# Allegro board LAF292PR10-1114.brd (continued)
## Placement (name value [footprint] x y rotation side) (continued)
CZ84  68P_0402_50V8J  [C_0402]  181.78 36.2 0 bottom
CZ85  68P_0402_50V8J  [C_0402]  178.48 37.3 90 bottom
CZ86  68P_0402_50V8J  [C_0402]  177.59 37.3 90 bottom
CZ87  68P_0402_50V8J  [C_0402]  176.7 37.3 90 bottom
CZ88  68P_0402_50V8J  [C_0402]  174.29 36.6 90 bottom
CZ89  68P_0402_50V8J  [C_0402]  173.4 36.6 90 bottom
CZ90  0.1U_0201_10V6K  [C_0201]  175.94 36.92 90 bottom
CZ91  0.1U_0201_10V6K  [C_0201]  179.24 37.17 90 bottom
CZ92  0.1U_0201_10V6K  [C_0201]  179.87 37.17 90 bottom
CZ100  1U_0402_6.3V6K  [C_0402]  162.22 92.54 0 top
CZ101  0.1U_0201_10V6K  [C_0201]  157.4 92.41 270 top
CZ102  1U_0402_6.3V6K  [C_0402]  95.18 46.88 90 top
CZ103  0.1U_0201_10V6K  [C_0201]  94.4 43.81 270 top
CZ104  0.1U_0402_10V7K  [C_0402]  92.28 39.93 0 top
CZ105  1U_0402_6.3V6K  [C_0402]  170.02 82.81 90 bottom
CZ106  0.1U_0201_10V6K  [C_0201]  175.11 79.16 0 bottom
CZ109  470P_0402_50V7K  [C_0402]  233.72 37.7 90 top
CZ112  0.1U_0201_10V6K  [C_0201]  236.26 36.19 270 top
CZ113  470P_0402_50V7K  [C_0402]  234.64 37.7 90 top
CZ114  1000P_0402_50V7K  [C_0402]  19.35 32.09 180 top
CZ115  0.1U_0201_10V6K  [C_0201]  19.5 32.82 180 top
CZ116  0.1U_0201_10V6K  [C_0201]  201.9 42.31 90 top
CZ117  470P_0402_50V7K  [C_0402]  202.66 42.4 90 top
CZ118  470P_0402_50V7K  [C_0402]  203.61 42.4 90 top
CZ119  0.1U_0201_10V6K  [C_0201]  204.37 42.31 90 top
CZ120  0.1U_0201_10V6K  [C_0201]  224.91 43.49 0 top
CZ121  470P_0402_50V7K  [C_0402]  225.01 42.68 270 top
CZ122  0.1U_0201_10V6K  [C_0201]  232.71 37.89 90 top
CZ124  2200P_0402_50V7K  [C_0402]  205.13 42.4 90 top
CZ125  0.1U_0201_10V6K  [C_0201]  256.79 34.66 0 top
CZ126  220P_0402_50V7K  [C_0402]  256.87 33.9 0 top
CZ127  1000P_0402_50V7K  [C_0402]  256.87 32.95 0 top
CZ128  0.1U_0201_10V6K  [C_0201]  256.79 32.19 0 top
CZ150  0.1U_0402_10V7K  [C_0402]  228.95 57.38 90 top
CZ151  0.1U_0402_10V7K  [C_0402]  227.99 57.38 90 top
CZ152  0.22U_0402_10V6K  [C_0402]  226.79 57.38 90 top
CZ153  0.22U_0402_10V6K  [C_0402]  225.84 57.38 90 top
CZ154  .1U_0402_16V7K  [C_0402]  232.05 62.54 0 top
CZ155  .1U_0402_16V7K  [C_0402]  223.69 61.86 90 top
CZ164  100P_0402_50V8J  [C_0402]  235.5 49.49 90 bottom
CZ165  100P_0402_50V8J  [C_0402]  232.17 51.05 0 top
CZ166  100P_0402_50V8J  [C_0402]  232.17 52 0 top
CZ167  0.1U_0201_10V6K  [C_0201]  103.04 91.74 90 top
CZ168  10U_0603_10V6M  [C_0603]  276.14 86.19 180 top
CZ169  0.1U_0201_10V6K  [C_0201]  276.13 87.14 0 top
CZ170  0.1U_0201_10V6K  [C_0201]  276.06 88.67 0 top
CZ180  68P_0402_50V8J  [C_0402]  32.28 85.45 0 bottom
CZ181  68P_0402_50V8J  [C_0402]  32.41 87.99 0 bottom
CZ182  68P_0402_50V8J  [C_0402]  32.35 83.91 0 bottom
CZ183  68P_0402_50V8J  [C_0402]  32.35 83.02 0 bottom
CZ184  68P_0402_50V8J  [C_0402]  32.35 82.13 0 bottom
CZ185  68P_0402_50V8J  [C_0402]  32.35 81.24 0 bottom
CZ186  0.1U_0201_10V6K  [C_0201]  32.45 84.69 0 bottom
CZ187  0.1U_0201_10V6K  [C_0201]  32.45 87.23 0 bottom
CZ188  0.1U_0201_10V6K  [C_0201]  82.58 90.63 90 bottom
CZ197  470P_0402_50V7K  [C_0402]  219.18 42.79 180 top
CZ198  100P_0402_50V8J  [C_0402]  225.47 89.49 270 top
CZ200  0.1U_0402_25V6K  [C_0402]  231.16 34.97 0 bottom
CZ300  68P_0402_50V8J  [C_0402]  226.62 72.11 180 top
CZ301  68P_0402_50V8J  [C_0402]  226.37 73.11 180 top
CZ302  68P_0402_50V8J  [C_0402]  226.37 74.06 180 top
CZ303  68P_0402_50V8J  [C_0402]  227.07 74.98 180 top
CZ304  68P_0402_50V8J  [C_0402]  229.4 78.57 180 top
CZ305  0.1U_0201_10V6K  [C_0201]  186.61 37.64 90 top
CZ306  470P_0402_50V7K  [C_0402]  185.03 36.15 180 top
DA1  AZ5125-02S.R7G_SOT23-3  [AZ5125-02SPR7G_SOT23-3]  281.14 33.52 270 top
DA2  AZ5125-02S.R7G_SOT23-3  [AZ5125-02SPR7G_SOT23-3]  283.2 29.58 90 top
DA3  AZ5123-02S.R7G_SOT23-3  [L03ESDL5V0CC3-2_SOT23-3]  280.94 39.33 270 top
DA6  AZ5125-02S.R7G_SOT23-3  [AZ5125-02SPR7G_SOT23-3]  286.45 23.45 90 top
DA7  AZ5125-02S.R7G_SOT23-3  [AZ5125-02SPR7G_SOT23-3]  295.72 23.43 90 top
DA8  RB751S-40 SOD-523  [AZ5125-01HPR7G_SOD523-2]  257.36 38.46 0 top
DC1  RB751S-40 SOD-523  [AZ5125-01HPR7G_SOD523-2]  167.68 34.3 270 top
DC2  RB751S-40 SOD-523  [AZ5125-01HPR7G_SOD523-2]  169.69 42.8 270 top
DE1  BZV55-B5V6_SOD80C2  [BZV55-B5V1_SOD80C2]  176.7 70.57 270 top
DE2  RB751S-40 SOD-523  [AZ5125-01HPR7G_SOD523-2]  262.93 82.09 270 top
DI1  AZ1045-04F_DFN2510P10E-10-9  [L05ESDL5V0NA-4_SLP2510P8-10-9]  15.48 22.2 270 bottom
DI2  -  [PESD5V0U2BT_SOT23-3]  24.88 24.75 90 top
DI4  AZ1045-04F_DFN2510P10E-10-9  [L05ESDL5V0NA-4_SLP2510P8-10-9]  280.96 70.72 90 top
DI5  -  [PESD5V0U2BT_SOT23-3]  278.96 73.36 90 top
DT1  DA2J10100L SOD323  [1N4148WS-7-F_SOD323-2]  31.01 31.68 180 top
DT2  DA2J10100L SOD323  [1N4148WS-7-F_SOD323-2]  31.01 33.46 180 top
DT3  DA2J10100L SOD323  [1N4148WS-7-F_SOD323-2]  25.05 33.45 270 top
DT4  AZ4024-02S_SOT23-3  [L30ESD24VC3-2_SOT23-3]  17.98 80.22 270 bottom
DT5  AZ5B75-01B.R7G CSP0603P2Y  [ESD8011MUT5G_X3DFN2-2-S]  13 86.48 90 top
DT6  AZ5B75-01B.R7G CSP0603P2Y  [ESD8011MUT5G_X3DFN2-2-S]  13 85.77 270 top
DT9  AZ5B75-01B.R7G CSP0603P2Y  [ESD8011MUT5G_X3DFN2-2-S]  13 79.37 90 top
DT10  AZ5B75-01B.R7G CSP0603P2Y  [ESD8011MUT5G_X3DFN2-2-S]  13 78.66 270 top
DT13  AZ5B75-01B.R7G CSP0603P2Y  [ESD8011MUT5G_X3DFN2-2-S]  13 86.48 90 bottom
DT14  AZ5B75-01B.R7G CSP0603P2Y  [ESD8011MUT5G_X3DFN2-2-S]  13 85.77 270 bottom
DT17  AZ5B75-01B.R7G CSP0603P2Y  [ESD8011MUT5G_X3DFN2-2-S]  13 78.66 270 bottom
DT18  AZ5B75-01B.R7G CSP0603P2Y  [ESD8011MUT5G_X3DFN2-2-S]  13 79.37 90 bottom
DT21  AZ4024-02S_SOT23-3  [L30ESD24VC3-2_SOT23-3]  16.01 61.05 270 bottom
DT22  AZ5B75-01B.R7G CSP0603P2Y  [ESD8011MUT5G_X3DFN2-2-S]  13 72.13 90 top
DT23  AZ5B75-01B.R7G CSP0603P2Y  [ESD8011MUT5G_X3DFN2-2-S]  13 71.42 270 top
DT26  AZ5B75-01B.R7G CSP0603P2Y  [ESD8011MUT5G_X3DFN2-2-S]  13 64.64 90 top
DT27  AZ5B75-01B.R7G CSP0603P2Y  [ESD8011MUT5G_X3DFN2-2-S]  13 63.93 270 top
DT30  AZ5B75-01B.R7G CSP0603P2Y  [ESD8011MUT5G_X3DFN2-2-S]  13 72.13 90 bottom
DT31  AZ5B75-01B.R7G CSP0603P2Y  [ESD8011MUT5G_X3DFN2-2-S]  13 71.42 270 bottom
DT34  AZ5B75-01B.R7G CSP0603P2Y  [ESD8011MUT5G_X3DFN2-2-S]  13 63.93 270 bottom
DT35  AZ5B75-01B.R7G CSP0603P2Y  [ESD8011MUT5G_X3DFN2-2-S]  13 64.64 90 bottom
DT38  DA2J10100L SOD323  [1N4148WS-7-F_SOD323-2]  26.83 33.45 270 top
DT41  AZ1045-04F_DFN2510P10E-10-9  [L05ESDL5V0NA-4_SLP2510P8-10-9]  13.56 82.02 270 top
DT42  AZ1045-04F_DFN2510P10E-10-9  [L05ESDL5V0NA-4_SLP2510P8-10-9]  14.07 84.14 90 bottom
DT43  AZ1045-04F_DFN2510P10E-10-9  [L05ESDL5V0NA-4_SLP2510P8-10-9]  13.56 67.03 270 top
DT44  AZ1045-04F_DFN2510P10E-10-9  [L05ESDL5V0NA-4_SLP2510P8-10-9]  14.07 69.16 90 bottom
DV1  BAT54CW SOT323  [BAT54CW_SOT323-3]  219.68 31.93 180 bottom
DV2  BAT54CW SOT323  [BAT54CW_SOT323-3]  216.88 31.93 180 bottom
DV3  BAT54CW SOT323  [BAT54CW_SOT323-3]  235.12 27.52 180 top
DV4  -  [PESD5V0U2BT_SOT23-3]  181.12 37.71 90 top
DZ1  RB751S-40 SOD-523  [AZ5125-01HPR7G_SOD523-2]  236.99 42.25 0 top
DZ2  RB751S-40 SOD-523  [AZ5125-01HPR7G_SOD523-2]  238.17 43.65 0 top
DZ5  RB751S-40 SOD-523  [AZ5125-01HPR7G_SOD523-2]  228.9 85.48 0 top
DZ6  RB751S-40 SOD-523  [AZ5125-01HPR7G_SOD523-2]  229.06 79.84 90 top
DZ7  RB751S-40 SOD-523  [AZ5125-01HPR7G_SOD523-2]  189.51 36.95 270 top
DZ8  RB751S-40 SOD-523  [AZ5125-01HPR7G_SOD523-2]  191.09 34.25 180 top
DZ9  -  [BAT54CW_SOT323-3]  236.58 29.3 270 bottom
DZ100  RB751S-40 SOD-523  [AZ5125-01HPR7G_SOD523-2]  233.3 66.11 180 top
DZ101  RB751S-40 SOD-523  [AZ5125-01HPR7G_SOD523-2]  233.3 64.09 180 top
DZ102  RB751S-40 SOD-523  [AZ5125-01HPR7G_SOD523-2]  233.85 56.49 180 top
DZ103  RB751S-40 SOD-523  [AZ5125-01HPR7G_SOD523-2]  233.66 54.85 180 top
DZ104  RB751S-40 SOD-523  [AZ5125-01HPR7G_SOD523-2]  246.28 80.1 0 top
DZ105  RB751S-40 SOD-523  [AZ5125-01HPR7G_SOD523-2]  246.32 81.82 0 top
DZ106  RB751S-40 SOD-523  [AZ5125-01HPR7G_SOD523-2]  255.25 50 180 top
DZ107  RB751S-40 SOD-523  [AZ5125-01HPR7G_SOD523-2]  263.82 46.82 180 top
FD1  FIDUCIAL MARK~D  [FIDUCIAL_C40M80]  18.58 17.26 0 top
FD2  FIDUCIAL MARK~D  [FIDUCIAL_C40M80]  18.58 17.26 180 bottom
FD3  FIDUCIAL MARK~D  [FIDUCIAL_C40M80]  266.74 87.84 0 top
FD4  FIDUCIAL MARK~D  [FIDUCIAL_C40M80]  255.8 88.83 180 bottom
H1  -  [H_3P8]  107.6 80 0 top
H2  -  [H_3P8]  107.6 57.86 0 top
H3  -  [H_3P8]  167.4 80 0 top
H4  -  [H_3P8]  167.4 57.9 0 top
H5  -  [H_1P1N]  117.15 83.46 0 top
H6  -  [H_1P1N]  158.26 60.35 0 top
H7  -  [H_7P0N]  277.95 79.4 0 top
H8  -  [H_7P0N]  276.55 46.9 0 top
H9  -  [H_2P3]  5.5 91.05 0 top
H11  -  [H_2P5]  54.1 91.55 0 top
H12  -  [H_2P3]  90.5 93.2 0 top
H13  -  [H_2P5]  134.43 92.45 0 top
H14  -  [H_2P3]  150.5 93.2 0 top
H16  -  [H_2P3]  234.9 94.9 0 top
H17  -  [H_2P5N]  291 82 0 top
H18  -  [H_2P3]  296 80.5 0 top
H19  -  [H_2P3]  5.5 59.85 0 top
H20  -  [H_2P3]  69.9 65.8 0 top
H24  -  [H_5P6]  7 4 0 top
H26  -  [H_2P3]  285 4 0 top
H27  -  [H_5P6]  294 4 0 top
H28  -  [H_1P3N]  9.5 75.45 0 top
H29  -  [H_1P3X1P8N]  9.5 59.85 180 top
H30  -  [H_0P8N]  296.5 54.7 0 top
H31  -  [H_0P8N]  295.35 55.5 0 top
H32  -  [H_0P9N]  282.3 46.3 0 top
H33  -  [H_1P1N]  284.5 43 0 top
H34  -  [H_3P2]  177.5 87 0 top
JAPS1  CVILU_CF4218FH0R0-05-NH  [CVILU_CF4218FH0R0-05-NH_18P-T]  194.84 42.28 180 top
JDEG1  JXT_FP241AH-010GAAM  [JXT_FP241AH-010GAAM_10P]  245.03 29.8 180 bottom
JEDP1  ACES_50398-04041-001  [ACES_50398-04041-001_40P]  228.25 38.55 180 bottom
JESPI  JXT_FP241AH-010GAAM  [JXT_FP241AH-010GAAM_10P]  192.48 30.94 0 top
JFAN1  ACES_50278-0040N-001  [ACES_50278-0040N-001_4P]  166.83 71.88 270 bottom
JHDMI1  CONCR_099A3AC19JBLCNF  [CONCR_099A3AC19JBLCNF_19P]  11.6 42.6 90 bottom
JHP1  SINGA_2SJ3095-085111F  [SINGA_2SJ3095-085111F_6P]  287.9 37.1 90 bottom
JIR1  ACES_50208-0060N-P01  [ACES_50208-0060N-P01_6P]  172 50.7 270 bottom
JKBTP1  CVILU_CF5020FD0RK-05-NH  [CVILU_CF5020FD0RK-05-NH_20P-T]  182.25 34.92 180 bottom
JLED1  CVILU_CF61062D0R0-05-NH  [CVILU_CF61062D0R0-05-NH_6P]  30.3 25.95 270 bottom
JNGFF1  LOTES_APCI0241-P001A  [LOTES_APCI0241-P001A_75P-T]  240.74 56.15 270 bottom
JNGFF2  LOTES_APCI0242-P001A  [LOTES_APCI0242-P001A_75P-T]  230.14 88.65 270 bottom
JNGFF3  LOTES_YPCI0016-P003A  [LOTES_YPCI0016-P003A_75P]  34.35 14.25 180 bottom
JPWR1  ACES_50208-0060N-P01  [ACES_50208-0060N-P01_6P]  297.5 25 180 bottom
JRTC1  ACES_50271-0020N-001  [ACES_50271-0020N-001_2P]  288.87 21.4 0 top
JSAR1  ACES_50208-0040N-001  [ACES_50208-0040N-001_4P]  234 49 90 bottom
JSD1  T-SOL_158-1240902600  [T-SOL_158-1240902600_23P-T]  286.35 51.47 90 top
JSEN2  ACES_50208-01201-P01  [ACES_50208-01201-P01_12P]  234 55.8 90 bottom
JSIM1  JAE_SF51S006V4B  [JAE_SF51S006V4B_10P-T]  285.13 53.31 270 bottom
JSPI1  ACES_50696-0200M-P01  [ACES_50696-0200M-P01_20P]  174.29 53.57 90 top
JSPK1  ACES_50278-00601-001  [ACES_50278-00601-001_6P-T]  281.95 18.13 270 bottom
JTAG1  @SHORT PADS~D  [SHORTPADS]  278.94 66.89 90 top
JTS1  ACES_50208-01001-P03  [ACES_50208-01001-P03_10P]  186.7 40.5 0 bottom
JTUN1  ACES_50208-00801-003  [ACES_50208-00801-003_8P]  29.3 82.5 0 bottom
JUSB1  SANTA_375230-1  [SANTA_375230-1_9P-T]  289.35 66 270 bottom
JUSB2  SANTA_375230-1  [SANTA_375230-1_9P-T]  11.65 27.6 90 bottom
JUSBC1  JAE_DX07SD24JJ2R1300~D  [JAE_DX07SD24JJ2R1300_24P]  7.55 85.32 270 top
JUSBC2  JAE_DX07SD24JJ2R1300~D  [JAE_DX07SD24JJ2R1300_24P]  7.55 70.82 270 top
JUSH1  CVILU_CF5026FD0RK-05-NH  [CVILU_CF5026FD0RK-05-NH_26P-T]  201.75 34.92 180 bottom
JXDP1  E-T_6601K-Y61N-04L  [E-T_6601K-Y61N-04L_61P]  76.47 91.73 180 top
LA5  BLM15PX600SN1D_2P  [MURAT_BLM15PX600SN1D_2P]  271.57 43.98 90 top
LA6  BLM15PX330SN1D_2P  [MURAT_BLM15PX330SN1D_2P]  289.09 24.85 180 top
LA7  BLM15PX330SN1D_2P  [MURAT_BLM15PX330SN1D_2P]  289.09 23.2 180 top
LA8  BLM15PX330SN1D_2P  [MURAT_BLM15PX330SN1D_2P]  298.09 24.89 180 top
LA9  BLM15PX330SN1D_2P  [MURAT_BLM15PX330SN1D_2P]  298.21 21.55 180 top
LA10  BLM15PX330SN1D_2P  [MURAT_BLM15PX330SN1D_2P]  279.06 39.33 90 top
LA11  BLM15PX330SN1D_2P  [MURAT_BLM15PX330SN1D_2P]  278.69 37.42 0 top
LA12  BLM15PX600SN1D_2P  [MURAT_BLM15PX600SN1D_2P]  259.95 30.22 0 top
LA13  HCB2012VF-601T20_2P  [TAI-T_HCB2012KF-121T50_2P]  267.75 44.28 0 top
LA14  BLM15PX600SN1D_2P  [MURAT_BLM15PX600SN1D_2P]  261.07 37.94 0 top
LC1  FBMA-11-100505-750A10T 0402  [MURAT_BLM15GA750SN1D_2P]  144.4 67.99 0 top
LC2  FBMA-11-100505-750A10T 0402  [MURAT_BLM15GA750SN1D_2P]  150.66 73.36 180 top
LGA1  -  [LNG2DMTR_LGA12_2X2]  272.5 89.1 0 top
LI3  MCM1012B900F06BP_4P  [INPAQ_MCM1012B900F06BP_4P]  27.08 26.25 180 top
LI7  MCM1012B900F06BP_4P  [INPAQ_MCM1012B900F06BP_4P]  273.74 73.74 0 top
LI8  EXC24CQ900U_4P  [PANAS_EXC24CQ900U_4P]  226.24 87.38 90 top
LI9  EXC24CQ900U_4P  [PANAS_EXC24CQ900U_4P]  237.91 53.28 0 bottom
LI16  HCM1012GH900BP_4P  [INPAQ_HCM1012GH900BP_4P]  225.85 80.48 0 top
LI17  HCM1012GH900BP_4P  [INPAQ_HCM1012GH900BP_4P]  225.85 78.57 0 top
LT1  0.6UH_MND-04ABIR60M-XGL_20%  [MAG_MND-04ABIR60M-XGL_2P]  28.02 67.6 180 bottom
LT2  1UH_LQM18NN1R0K00D_10%  [MURAT_LQM18NN1R0K00D_2P]  21.09 54.06 90 bottom
LV1  BLM15BB221SN1D_2P  [MURAT_BLM15BB221SN1D_2P]  221.33 36.42 270 bottom
LV3  HCM1012GH900BP_4P  [TAIYO_MCF12102G900-T_4P-NPM]  19.13 41.88 180 top
LV6  HCM1012GH900BP_4P  [TAIYO_MCF12102G900-T_4P-NPM]  19.13 43.91 180 top
LV9  HCM1012GH900BP_4P  [TAIYO_MCF12102G900-T_4P-NPM]  19.13 45.95 180 top
LV12  HCM1012GH900BP_4P  [TAIYO_MCF12102G900-T_4P-NPM]  19.13 47.98 180 top
LV27  EXC24CQ900U_4P  [PANAS_EXC24CQ900U_4P]  176.89 38.42 270 top
LV31  4.3NH_LQG15HS4N3S02D_0.3NH  [MURAT_LQG15HS4N3S02D_2P]  18.97 41.74 180 top
LV32  4.3NH_LQG15HS4N3S02D_0.3NH  [MURAT_LQG15HS4N3S02D_2P]  18.97 42.63 180 top
LV33  4.3NH_LQG15HS4N3S02D_0.3NH  [MURAT_LQG15HS4N3S02D_2P]  18.97 43.77 180 top
LV34  4.3NH_LQG15HS4N3S02D_0.3NH  [MURAT_LQG15HS4N3S02D_2P]  18.97 44.66 180 top
LV35  4.3NH_LQG15HS4N3S02D_0.3NH  [MURAT_LQG15HS4N3S02D_2P]  18.92 45.81 180 top
LV36  4.3NH_LQG15HS4N3S02D_0.3NH  [MURAT_LQG15HS4N3S02D_2P]  18.92 46.69 180 top
LV37  15NH_LQG15HS15NJ02D_450MA_5%  [MURAT_LQG15HS15NJ02D_2P]  18.97 47.74 180 top
LV38  15NH_LQG15HS15NJ02D_450MA_5%  [MURAT_LQG15HS15NJ02D_2P]  18.97 48.76 180 top
LZ1  EXC24CQ900U_4P  [PANAS_EXC24CQ900U_4P]  225.44 34.48 0 bottom
NOREF  -  []  287.19 12.02 0 top
NOREF#2  -  []  111.76 48.46 0 top
NOREF#3  -  []  81.56 74.93 0 top
NOREF#4  -  []  103.74 31.95 0 top
NOREF#5  -  []  63 -14.54 0 top
NOREF#6  -  []  6.3 11.54 90 top
NOREF#7  -  []  74.26 59.5 0 top
NOREF#8  -  []  270.55 86.64 180 bottom
NOREF#9  -  []  259.44 68.03 180 bottom
NOREF#10  -  []  247.78 83 180 bottom
NOREF#11  -  []  272.18 75.9 180 bottom
PBATT1  DEREN_40-42507-01001RHF  [DEREN_40-42507-01001RHF_10P-T]  59.12 41.55 180 bottom
PC1  2200P_0402_50V7K  [C_0402]  62.25 44.75 0 bottom
PC2  2200P_0402_50V7K  [C_0402]  289.86 23.78 270 bottom
PC3  1U_0603_25V6K  [C_0603]  285.56 25.21 0 bottom
PC100  0.1U_0402_25V6  [C_0402]  72.48 44.79 0 top
PC102  0.1U_0603_25V7K  [C_0603]  74.91 41.49 180 top
PC103  2200P_0402_50V7K  [C_0402]  72.48 43.9 0 top
PC104  10U_0603_25V6M  [C_0603]  73 47.28 0 top
PC105  10U_0603_25V6M  [C_0603]  73 47.28 0 bottom
PC106  22U_0603_6.3V6M  [C_0603]  78.08 36.15 0 top
PC107  22U_0603_6.3V6M  [C_0603]  78.08 36.15 0 bottom
PC108  22U_0603_6.3V6M  [C_0603]  78.08 37.42 0 bottom
PC109  22U_0603_6.3V6M  [C_0603]  78.08 34.88 0 bottom
PC110  22U_0603_6.3V6M  [C_0603]  78.08 37.42 0 top
PC111  4.7U_0603_6.3V6K  [C_0603]  77.12 42.25 270 bottom
PC112  680P_0603_50V7K  [C_0603]  76.12 41.41 90 top
PC113  1000P_0402_50V7K  [C_0402]  77.47 44.23 0 bottom
PC114  0.1U_0603_25V7K  [C_0603]  50.91 67.52 0 top
PC115  0.1U_0402_25V6  [C_0402]  48.89 74.38 180 bottom
PC116  2200P_0402_50V7K  [C_0402]  48.89 73.36 180 bottom
PC117  10U_0603_16VAK  [C_0603]  49.95 74.13 0 bottom
PC118  10U_0603_16VAK  [C_0603]  49.95 74.13 0 top
PC119  4.7U_0603_6.3V6K  [C_0603]  55.22 68.41 0 bottom
PC120  22U_0603_6.3VAM  [C_0603]  46.08 61.07 0 bottom
PC121  22U_0603_6.3VAM  [C_0603]  45.06 63.59 180 bottom
PC122  22U_0603_6.3VAM  [C_0603]  45.06 61.07 180 bottom
PC123  22U_0603_6.3VAM  [C_0603]  45.06 62.32 180 bottom
PC124  22U_0603_6.3VAM  [C_0603]  45.06 62.32 180 top
PC125  680P_0603_50V7K  [C_0603]  54.97 63.33 180 top
PC126  4.7U_0603_6.3V6K  [C_0603]  55.22 69.68 0 bottom
PC127  1000P_0402_50V7K  [C_0402]  55.47 71.71 0 bottom
PC128  4.7U_0603_6.3V6K  [C_0603]  77.45 46.31 0 bottom
PC129  22U_0603_6.3V6M  [C_0603]  78.08 34.88 0 top
PC130  22U_0603_6.3VAM  [C_0603]  46.08 61.07 0 top
PC131  82P_0402_50V8J  [C_0402]  73.88 45.68 0 top
PC132  82P_0402_50V8J  [C_0402]  50.41 72.92 0 top
PC133  1000P_0402_50V7K  [C_0402]  75.93 50.62 270 bottom
PC134  1000P_0402_50V7K  [C_0402]  75.04 50.62 270 bottom
PC135  1U_0402_25V6K  [C_0402]  53 79 90 bottom
PC136  1U_0402_25V6K  [C_0402]  51.99 79 90 bottom
PC137  1000P_0402_50V7K  [C_0402]  62.27 59.27 90 bottom
PC138  1000P_0402_50V7K  [C_0402]  54.02 79 90 bottom
PC139  1U_0402_25V6K  [C_0402]  50.97 79 90 bottom
PC140  1U_0402_25V6K  [C_0402]  55.03 79 90 bottom
PC150  22U_0603_6.3VAM  [C_0603]  45.06 61.07 180 top
PC151  22U_0603_6.3VAM  [C_0603]  45.06 63.59 180 top
PC161  22U_0603_6.3V6M  [C_0603]  78.08 38.69 0 bottom
PC162  22U_0603_6.3V6M  [C_0603]  78.08 38.69 0 top
PC163  22U_0603_6.3VAM  [C_0603]  48.49 61.07 0 bottom
PC164  22U_0603_6.3VAM  [C_0603]  48.49 61.07 0 top
PC200  10U_0603_25V6M  [C_0603]  84.05 48.47 0 top
PC201  10U_0603_25V6M  [C_0603]  84.05 48.47 0 bottom
PC202  82P 50V J NPO 0402  [C_0402]  84.55 47.33 0 bottom
PC203  0.1U 25V K X5R 0402  [C_0402]  84.55 47.33 0 top
PC204  680P_0603_50V7K  [C_0603]  86.02 35.58 270 top
PC205  0.1U_0603_16V7K  [C_0603]  80.5 36.03 0 top
PC206  1U_0402_6.3V6K  [C_0402]  81.27 41.22 180 bottom
PC207  2.2U_0402_6.3V6M  [C_0402]  81.53 42.12 180 bottom
PC208  330P_0402_50V7K  [C_0402]  80.54 44.79 0 bottom
PC209  22U_0603_6.3V6M  [C_0603]  87.1 41.49 0 bottom
PC210  22U_0603_6.3V6M  [C_0603]  88.05 36.47 90 top
PC211  22U_0603_6.3V6M  [C_0603]  88.05 33.04 270 top
PC212  22U_0603_6.3V6M  [C_0603]  88.05 36.47 90 bottom
PC213  22U_0603_6.3V6M  [C_0603]  88.05 34.06 90 bottom
PC214  10U_0603_6.3V6M  [C_0603]  88.05 33.04 270 bottom
PC216  2200P_0402_50V7K  [C_0402]  90.47 32.55 270 bottom
PC217  100P_0402_50V8J  [C_0402]  89.58 32.55 270 bottom
PC218  1U_0402_10V6K  [C_0402]  87.67 44.74 270 bottom
PC219  22U_0603_6.3V6M  [C_0603]  87.1 42.76 0 bottom
PC221  0.1U_0402_10V7K  [C_0402]  87.98 46.19 0 top
PC222  0.1U_0402_10V7K  [C_0402]  87.98 44.41 0 top
PC223  10U_0603_6.3V6M  [C_0603]  88.05 34.06 90 top
PC301  100P_0402_50V8J  [C_0402]  60.16 72.73 0 top
PC302  680P_0603_50V7K  [C_0603]  56.93 63.31 270 bottom
PC303  100P_0402_50V8J  [C_0402]  60.16 71.84 0 top
PC304  0.1U_0201_10V6K  [C_0201]  58.83 70.68 0 bottom
PC305  10U_0603_25V6M  [C_0603]  59.48 73.68 90 bottom
PC306  10U_0603_25V6M  [C_0603]  59.48 73.68 90 top
PC307  330P_0402_50V7K  [C_0402]  66.34 70.5 90 bottom
PC308  22U_0603_6.3V6M  [C_0603]  63.73 64.22 0 bottom
PC309  22U_0603_6.3V6M  [C_0603]  63.73 64.22 0 top
PC310  22U_0603_6.3V6M  [C_0603]  63.73 65.49 0 top
PC311  22U_0603_6.3V6M  [C_0603]  63.73 65.49 0 bottom
PC312  1U_0402_6.3V6K  [C_0402]  64.86 69.43 0 bottom
PC313  2.2U_0402_6.3V6M  [C_0402]  63.67 69.12 270 bottom
PC401  470P_0402_50V7K  [C_0402]  182.82 29.52 0 top
PC402  0.1U_0402_25V6  [C_0402]  170.65 26.31 0 top
PC403  10U_0603_10V6M  [C_0603]  172.83 28.72 270 top
PC404  10U_0603_10V6M  [C_0603]  174.22 28.72 270 top
PC406  22U_0603_6.3V6M  [C_0603]  184.83 26.63 0 top
PC407  22U_0603_6.3V6M  [C_0603]  184.95 28.15 90 top
PC408  0.1U_0402_25V6  [C_0402]  172.66 29.73 90 top
PC409  2200P_0402_50V7K  [C_0402]  171.62 28.09 270 top
PC410  470P_0402_50V7K  [C_0402]  177.21 32.42 0 top
PC411  0.1U_0402_25V6  [C_0402]  167.82 33.55 0 bottom
PC412  10U_0603_10V6M  [C_0603]  166.38 35.78 90 bottom
PC413  10U_0603_10V6M  [C_0603]  165.17 35.78 90 bottom
PC415  22U_0603_6.3V6M  [C_0603]  168.11 30.26 90 bottom
PC417  0.1U_0402_25V6  [C_0402]  167.4 37.13 0 bottom
PC418  2200P_0402_50V7K  [C_0402]  167.39 36.24 0 bottom
PC419  470P_0402_50V7K  [C_0402]  159.47 28.01 180 bottom
PC420  470P_0402_50V7K  [C_0402]  156.59 31.04 180 top
PC421  82P_0402_50V8J  [C_0402]  167.39 38.08 0 bottom
PC422  22U_0603_6.3V6M  [C_0603]  186.35 28.15 90 top
PC424  22U_0603_6.3V6M  [C_0603]  168.11 30.26 90 top
PC427  22U_0603_6.3V6M  [C_0603]  168.11 28.79 270 top
PC501  22U_0603_6.3V6M  [C_0603]  218.54 28.13 90 top
PC502  22U_0603_6.3V6M  [C_0603]  207.88 30.69 180 top
PC503  68P_0402_50V8J  [C_0402]  209.08 26.25 90 top
PC504  22U_0603_6.3V6M  [C_0603]  217.15 28.1 90 top
PC505  0.1U_0402_16V7K  [C_0402]  210.37 32.4 0 top
PC506  680P_0402_50V7K  [C_0402]  214.23 31.59 180 top
PC513  .1U_0402_16V7K  [C_0402]  80.22 55.89 180 top
PC514  4.7U_0603_6.3V6K  [C_0603]  77.2 53.08 270 top
PC515  0.01UF_0402_25V7K  [C_0402]  82.09 49.12 90 top
PC516  22U_0603_6.3V6M  [C_0603]  77.55 49.62 0 top
PC601  680P_0402_50V7K  [C_0402]  75.27 70.33 270 bottom
PC602  0.1U_0402_25V6  [C_0402]  65.47 79.54 0 bottom
PC603  1U_0603_10V6K  [C_0603]  67.67 75.47 180 bottom
PC604  0.22U_0603_25V7K  [C_0603]  67.67 74.25 180 bottom
PC605  47P_0402_50V8J  [C_0402]  65.44 77.85 0 top
PC606  100U_D2_20VM_R55M  [C_D2]  82 74.01 90 bottom
PC608  10U_0603_25V6M  [C_0603]  84.64 53.88 89.9 top
PC611  0.22U_0603_16V7K  [C_0603]  87.39 55.37 270 top
PC612  10U_0603_25V6M  [C_0603]  84.47 53.84 90.1 bottom
PC613  330P_0402_50V7K  [C_0402]  70.65 78.75 90 top
PC614  2200P_0402_50V7K  [C_0402]  69.06 83.02 270 top
PC616  33P_0402_50V8J  [C_0402]  71.54 78.62 90 top
PC617  1200P_0402_50V7K  [C_0402]  71.83 82.93 180 top
PC618  330P_0402_50V7K  [C_0402]  70.94 83.82 0 top
PC619  0.01UF_0402_25V7K  [C_0402]  72.43 78.7 90 top
PC620  0.082U_0402_16V7K  [C_0402]  71.71 82.08 270 top
PC621  680P_0402_50V7K  [C_0402]  68.97 84.33 0 top
PC622  680P_0603_50V7K  [C_0603]  97.69 56.26 0 top
PC624  0.033U_0402_16V7K  [C_0402]  74.3 80.52 90 top
PC625  330P_0402_50V7K  [C_0402]  74.45 77.39 0 top
PC626  0.01U_0402_25V7K  [C_0402]  73.41 81.17 90 top
PC627  2200P_0402_50V7K  [C_0402]  72.1 82.08 270 bottom
PC628  33P 50V J NPO 0402  [C_0402]  73.07 73.8 90 top
PC629  2200P_0402_50V7K  [C_0402]  77.7 79.01 270 bottom
PC630  2200P_0402_50V7K  [C_0402]  76.12 74.13 270 bottom
PC631  4700P_0402_25V7K  [C_0402]  73.01 70.61 0 top
PC632  1000P_0402_50V7K  [C_0402]  67.97 72.35 270 bottom
PC633  4700P 50V K X7R 0402  [C_0402]  70.64 72.36 270 bottom
PC635  0.022U_0402_16V7K  [C_0402]  73.86 82.08 270 bottom
PC636  33P_0402_50V8J  [C_0402]  74.45 76.49 0 top
PC637  0.033U 25V K X7R 0402  [C_0402]  69.74 72.36 270 bottom
PC638  0.022U_0402_16V7K  [C_0402]  75.19 81.44 270 top
PC639  1500P_0402_50V7K  [C_0402]  78.54 76.54 270 top
PC640  2200P_0402_50V7K  [C_0402]  74.41 70.29 180 bottom
PC641  .1U_0402_16V7K  [C_0402]  76.07 80.64 0 top
PC642  0.033U_0402_16V7K  [C_0402]  76.77 73.3 0 top
PC643  330P_0402_50V7K  [C_0402]  74.39 73.36 0 top
PC644  .1U_0402_16V7K  [C_0402]  69.98 70.56 0 bottom
PC645  .1U_0402_16V7K  [C_0402]  78.54 73.28 90 top
PC646  0.01U_0402_25V7K  [C_0402]  76.77 74.19 0 top
PC647  680P_0402_50V7K  [C_0402]  77.64 78.62 270 top
PC649  0.01UF_0402_25V7K  [C_0402]  71.54 73.8 90 top
PC650  0.082U_0402_16V7K  [C_0402]  72.37 71.45 90 bottom
PC651  330P_0402_50V7K  [C_0402]  78.54 78.28 270 top
PC652  330P_0402_50V7K  [C_0402]  72.62 70.61 270 bottom
PC653  0.082U_0402_16V7K  [C_0402]  77.97 75.4 180 bottom
PC654  0.01UF_0402_25V7K  [C_0402]  74.45 75.59 0 top
PC655  0.22U_0603_16V7K  [C_0603]  85.92 75.56 0 bottom
PC656  10U_0603_16VAK  [C_0603]  92.3 79.77 0 top
PC657  10U_0603_16VAK  [C_0603]  92.3 79.77 0 bottom
PC658  10U_0603_16VAK  [C_0603]  92.32 78.51 0 top
PC659  0.1U_0402_25V6K~D  [C_0402]  72.5 58.64 270 bottom
PC660  2200P_0402_50V7K  [C_0402]  71.61 58.64 270 bottom
PC661  1U_0402_10V6K  [C_0402]  89.79 70.27 0 bottom
PC662  680P_0603_50V7K  [C_0603]  89.21 82.41 180 bottom
PC663  0.22U_0603_16V7K  [C_0603]  89.1 54.91 90 bottom
PC664  10U_0603_16VAK  [C_0603]  86.48 57.73 90 bottom
PC665  10U_0603_16VAK  [C_0603]  85.19 57.73 90 bottom
PC669  1U_0402_10V6K  [C_0402]  92.67 55.81 180 bottom
PC670  680P_0603_50V7K  [C_0603]  92.65 63.36 90 top
PC671  0.22U_0603_16V7K  [C_0603]  83.78 61.65 90 bottom
PC672  10U_0603_16VAK  [C_0603]  81.11 65.23 307.5 bottom
PC673  10U_0603_16VAK  [C_0603]  80.43 66.1 127.2 bottom
PC674  10U_0603_16VAK  [C_0603]  86.48 57.73 90 top
PC675  10U_0603_16VAK  [C_0603]  85.19 57.73 90 top
PC677  1U_0402_10V6K  [C_0402]  86.94 62.87 180 bottom
PC678  680P_0603_50V7K  [C_0603]  81.93 69.43 270 bottom
PC682  10U_0603_16VAK  [C_0603]  92.32 78.51 0 bottom
PC683  10U_0603_16VAK  [C_0603]  81.24 65.31 307.5 top
PC684  10U_0603_16VAK  [C_0603]  80.55 66.18 127.2 top
PC685  1U_0402_10V6K  [C_0402]  85.51 50.1 180 bottom
PC686  0.1U_0402_25V6  [C_0402]  88.37 77.69 180 bottom
PC687  0.1U_0402_25V6  [C_0402]  85.15 56.75 0 bottom
PC688  0.1U_0402_25V6  [C_0402]  82.1 66.13 90 bottom
PC689  1000P_0402_50V7K  [C_0402]  64.39 59.1 90 top
PC690  1000P_0402_50V7K  [C_0402]  67.08 59.39 90 top
PC691  1U_0402_25V6K  [C_0402]  66.19 59.37 90 top
PC692  1U_0402_25V6K  [C_0402]  65.29 59.37 90 top
PC693  0.1U_0402_25V6K~D  [C_0402]  87.33 80.06 90 bottom
PC694  2200P_0402_50V7K  [C_0402]  88.28 80.06 90 bottom
PC695  82P_0402_50V8J  [C_0402]  85.27 80.06 90 bottom
PC696  82P_0402_50V8J  [C_0402]  86.36 80.06 90 bottom
PC697  100U_D2_20VM_R55M  [C_D2]  77.2 65.06 308.1 bottom
PC902  0.1U_0402_25V6  [C_0402]  48.38 58.29 90 top
PC903  2200P_0402_50V7K  [C_0402]  49.27 58.29 90 top
PC904  10U_0603_25V6M  [C_0603]  50.88 55.97 270 top
PC905  10U_0603_25V6M  [C_0603]  54.45 62.05 0 bottom
PC906  10U_0603_25V6M  [C_0603]  50.33 58.26 90 top
PC909  15U_B2_25VM_R100M  [C_B2]  47.86 58.87 0 bottom
PC911  10U_0603_25V6M  [C_0603]  50.88 55.97 270 bottom
PC913  10U_0603_16VAK  [C_0603]  64.34 55.36 270 top
PC914  10U_0603_16VAK  [C_0603]  69.41 55.58 180 bottom
PC915  10U_0603_16VAK  [C_0603]  69.41 55.58 180 top
PC916  10U_0603_16VAK  [C_0603]  63.34 58.78 90 top
PC917  10U_0603_16VAK  [C_0603]  63.34 58.78 90 bottom
PC918  10U_0603_16VAK  [C_0603]  65.6 55.56 0 bottom
PC919  10U_0603_16VAK  [C_0603]  65.6 55.56 0 top
PC920  10U_0603_16VAK  [C_0603]  64.34 55.36 270 bottom
PC925  4.7U 6.3V M X5R 0402  [C_0402]  52.09 34.02 90 top
PC926  1U 25V K X5R 0402  [C_0402]  51.83 32.67 180 top
PC927  1U 25V K X5R 0402  [C_0402]  51.81 35.98 180 top
PC928  0.1U_0402_25V6  [C_0402]  61.76 57.24 270 bottom
PC929  2200P_0402_50V7K  [C_0402]  70.34 55.62 0 top
PC930  0.22U_0603_25V7K  [C_0603]  50.4 38.21 0 top
PC931  1U_0603_25V6  [C_0603]  61.97 30.38 90 top
PC932  1U_0402_6.3V6K  [C_0402]  51.83 40.89 270 top
PC933  1U_0402_6.3V6K  [C_0402]  53.34 33.08 270 top
PC934  0.22U_0603_25V7K  [C_0603]  55.06 41.98 270 top
PC935  10U_0603_16VAK  [C_0603]  58.4 53.3 180 top
PC936  10U_0603_16VAK  [C_0603]  58.4 54.57 180 top
PC937  4700P_0402_25V7K  [C_0402]  57.57 52.16 0 top
PC938  10P_0402_50V8J  [C_0402]  59.86 32.15 270 top
PC939  0.1U_0402_25V6  [C_0402]  57.01 40.56 90 top
PC940  680P_0603_50V7K  [C_0603]  52.46 53.4 180 top
PC941  680P_0603_50V7K  [C_0603]  69.51 47.46 0 top
PC942  1U 25V K X5R 0402  [C_0402]  56.49 42.93 90 top
PC943  560P_0402_50V7K  [C_0402]  62.2 36.53 0 top
PC944  .012U 16V K X7R 0402  [C_0402]  62.2 37.42 0 top
PC945  1U 25V K X5R 0402  [C_0402]  58.78 42.01 180 top
PC946  0.22U_0402_25V6K  [C_0402]  59.8 43.01 90 top
PC947  0.1U_0402_25V6  [C_0402]  63.12 40.34 180 top
PC949  0.1U_0402_10V7K  [C_0402]  64.94 33.79 90 top
PC950  0.1U_0402_25V6  [C_0402]  60.51 40.34 180 top
PC951  10U_0603_25V6M  [C_0603]  50.33 58.26 90 bottom
PC952  10U_0603_25V6M  [C_0603]  54.45 62.05 0 top
PC955  0.1U 25V K X5R 0402  [C_0402]  54.45 43.01 90 top
PC956  0.1U_0402_25V6  [C_0402]  70.71 56.43 90 bottom
PC957  0.1U_0402_25V6  [C_0402]  128.5 28.27 90 top
PC958  0.1U_0402_25V6  [C_0402]  156.86 27 90 bottom
PC959  82P_0402_50V8J  [C_0402]  77.87 53.15 90 bottom
PC960  82P_0402_50V8J  [C_0402]  126.6 28.27 90 top
PC961  82P_0402_50V8J  [C_0402]  155.94 27 90 bottom
PC962  2200P_0402_50V7K  [C_0402]  76.82 50.62 270 bottom
PC963  2200P_0402_50V7K  [C_0402]  127.55 28.27 90 top
PC986  1000P_0402_50V7K  [C_0402]  64.69 61.55 90 top
PC987  1000P_0402_50V7K  [C_0402]  64.25 61.17 180 bottom
PC988  1U_0402_25V6K  [C_0402]  65.57 61.55 90 top
PC989  1U_0402_25V6K  [C_0402]  66.51 61.58 0 top
PC990  15U_B2_25VM_R100M  [C_B2]  72.17 55.12 127.2 bottom
PC1001  22U_0603_6.3V6M  [C_0603]  136.26 68.41 90 top
PC1002  22U_0603_6.3V6M  [C_0603]  137.47 68.41 90 top
PC1003  22U_0603_6.3V6M  [C_0603]  133.62 74.57 270 top
PC1004  22U_0603_6.3V6M  [C_0603]  135.03 72.18 270 top
PC1005  22U_0603_6.3V6M  [C_0603]  132.62 72.18 270 top
PC1006  22U_0603_6.3V6M  [C_0603]  132.64 68.41 90 top
PC1007  22U_0603_6.3V6M  [C_0603]  100.51 69.73 90 bottom
PC1008  22U_0603_6.3V6M  [C_0603]  100.44 73.5 270 bottom
PC1009  22U_0603_6.3V6M  [C_0603]  101.71 68.77 270 top
PC1010  22U_0603_6.3V6M  [C_0603]  100.44 73.5 270 top
PC1011  22U_0603_6.3V6M  [C_0603]  100.51 69.73 90 top
PC1012  22U_0603_6.3V6M  [C_0603]  101.66 73.5 270 top
PC1013  22U_0603_6.3V6M  [C_0603]  101.66 73.5 270 bottom
PC1014  22U_0603_6.3V6M  [C_0603]  115.77 74.65 180 top
PC1015  22U_0603_6.3V6M  [C_0603]  121.81 71.72 270 top
PC1016  22U_0603_6.3V6M  [C_0603]  121.32 74.06 270 top
PC1017  22U_0603_6.3V6M  [C_0603]  122.52 74.07 270 top
PC1018  22U_0603_6.3V6M  [C_0603]  114.62 71.07 270 top
PC1019  22U_0603_6.3V6M  [C_0603]  115.05 73.43 270 top
PC1020  22U_0603_6.3V6M  [C_0603]  113.85 73.43 270 top
PC1021  22U_0603_6.3V6M  [C_0603]  112.2 71.07 270 top
PC1022  22U_0603_6.3V6M  [C_0603]  123.02 71.71 270 top
PC1023  22U_0603_6.3V6M  [C_0603]  112.65 73.44 270 top
PC1024  22U_0603_6.3V6M  [C_0603]  125.01 74.06 270 top
PC1025  22U_0603_6.3V6M  [C_0603]  100.16 53.36 270 bottom
PC1026  22U_0603_6.3V6M  [C_0603]  124.23 71.72 270 top
PC1030  1U_0201_6.3V6M  [C_0201]  133.47 78.18 0 top
PC1031  1U_0201_6.3V6M  [C_0201]  137.61 65.73 0 top
PC1032  1U_0201_6.3V6M  [C_0201]  137.17 64.6 0 top
PC1033  1U_0201_6.3V6M  [C_0201]  138.42 68.59 0 top
PC1034  1U_0201_6.3V6M  [C_0201]  134.85 76.82 0 top
PC1035  1U_0201_6.3V6M  [C_0201]  135.24 78.75 180 top
PC1036  1U_0201_6.3V6M  [C_0201]  133.37 76.82 0 top
PC1037  1U_0201_6.3V6M  [C_0201]  136.41 78.18 180 top
PC1038  1U_0201_6.3V6M  [C_0201]  137.63 65.16 0 top
PC1039  1U_0201_6.3V6M  [C_0201]  133.04 66.9 180 top
PC1040  1U_0201_6.3V6M  [C_0201]  115.95 72.19 270 top
PC1041  1U_0201_6.3V6M  [C_0201]  124.86 76.88 0 top
PC1042  1U_0201_6.3V6M  [C_0201]  123.64 76.88 0 top
PC1043  1U_0201_6.3V6M  [C_0201]  118.4 74.97 270 top
PC1044  1U_0201_6.3V6M  [C_0201]  119.71 74.97 270 top
PC1045  1U_0201_6.3V6M  [C_0201]  122.45 76.91 0 top
PC1046  1U_0201_6.3V6M  [C_0201]  121.24 76.91 0 top
PC1047  1U_0201_6.3V6M  [C_0201]  119.72 72.53 90 top
PC1048  1U_0201_6.3V6M  [C_0201]  117.22 72.74 270 top
PC1049  1U_0201_6.3V6M  [C_0201]  118.42 73.23 270 top
PC1050  1U_0201_6.3V6M  [C_0201]  138.7 71.36 0 top
PC1051  1U_0201_6.3V6M  [C_0201]  137.04 78.16 0 top
PC1052  1U_0201_6.3V6M  [C_0201]  138.03 76.87 180 top
PC1053  1U_0201_6.3V6M  [C_0201]  138.77 76.9 0 top
PC1054  1U_0201_6.3V6M  [C_0201]  136.27 76.87 0 top
PC1055  1U_0201_6.3V6M  [C_0201]  117.13 74.96 270 top
PC1056  1U_0201_6.3V6M  [C_0201]  123.51 68.51 270 top
PC1057  22U_0603_6.3V6M  [C_0603]  141.77 67.78 180 top
PC1058  22U_0603_6.3V6M  [C_0603]  98.43 50.96 270 bottom
PC1059  22U_0603_6.3V6M  [C_0603]  99.64 50.96 270 top
PC1060  22U_0603_6.3V6M  [C_0603]  141.47 70.33 180 top
PC1061  22U_0603_6.3V6M  [C_0603]  138.53 74.57 270 top
PC1062  220U_D7_2VM_R4.5M  [C_D7]  101.41 83.85 180 bottom
PC1063  220U_D7_2VM_R4.5M  [C_D7]  108.37 68.69 90 bottom
PC1064  22U_0603_6.3V6M  [C_0603]  137.31 74.57 270 top
PC1065  22U_0603_6.3V6M  [C_0603]  137.5 72.22 270 top
PC1066  22U_0603_6.3V6M  [C_0603]  136.24 72.18 270 top
PC1067  22U_0603_6.3V6M  [C_0603]  136.09 74.57 270 top
PC1068  22U_0603_6.3V6M  [C_0603]  134.86 74.57 270 top
PC1069  22U_0603_6.3V6M  [C_0603]  133.83 72.18 270 top
PC1070  22U_0603_6.3V6M  [C_0603]  133.85 68.41 90 top
PC1071  22U_0603_6.3V6M  [C_0603]  135.05 68.41 90 top
PC1072  22U_0603_6.3V6M  [C_0603]  102.93 70.79 90 top
PC1073  22U_0603_6.3V6M  [C_0603]  101.71 68.77 270 bottom
PC1074  22U_0603_6.3V6M  [C_0603]  102.92 68.77 270 top
PC1075  22U_0603_6.3V6M  [C_0603]  102.93 70.79 90 bottom
PC1076  22U_0603_6.3V6M  [C_0603]  100.5 68.78 270 top
PC1077  22U_0603_6.3V6M  [C_0603]  132.41 74.57 270 top
PC1078  22U_0603_6.3V6M  [C_0603]  100.5 68.78 270 bottom
PC1079  22U_0603_6.3V6M  [C_0603]  131.11 72.54 270 top
PC1080  22U_0603_6.3V6M  [C_0603]  101.71 69.73 90 bottom
PC1081  22U_0603_6.3V6M  [C_0603]  101.71 69.73 90 top
PC1082  22U_0603_6.3V6M  [C_0603]  102.92 68.77 270 bottom
PC1083  1U_0201_6.3V6M  [C_0201]  139.11 77.64 0 top
PC1084  1U_0201_6.3V6M  [C_0201]  139.11 78.22 0 top
PC1085  1U_0201_6.3V6M  [C_0201]  134.21 64.37 180 top
PC1086  1U_0201_6.3V6M  [C_0201]  136.42 78.76 180 top
PC1087  1U_0201_6.3V6M  [C_0201]  133.46 78.75 0 top
PC1088  1U_0201_6.3V6M  [C_0201]  138.7 70.21 0 top
PC1089  1U_0201_6.3V6M  [C_0201]  138.7 70.78 0 top
PC1090  1U_0201_6.3V6M  [C_0201]  132.51 78.63 90 top
PC1091  1U_0201_6.3V6M  [C_0201]  138.42 69.17 0 top
PC1092  1U_0201_6.3V6M  [C_0201]  136.48 67.65 180 top
PC1093  1U_0201_6.3V6M  [C_0201]  137.08 67.63 0 top
PC1094  1U_0201_6.3V6M  [C_0201]  135.24 78.18 180 top
PC1095  1U_0201_6.3V6M  [C_0201]  132.74 76.83 180 top
PC1096  1U_0201_6.3V6M  [C_0201]  133.44 67.62 0 top
PC1097  1U_0201_6.3V6M  [C_0201]  134.33 64.94 180 top
PC1098  1U_0201_6.3V6M  [C_0201]  132.4 77.59 180 top
PC1099  1U_0201_6.3V6M  [C_0201]  134.62 67.62 0 top
PC1126  1U_0201_6.3V6M  [C_0201]  137.03 78.74 0 top
PC1127  220U_D7_2VM_R4.5M  [C_D7]  96.8 73.67 90 top
PC1128  220U_D7_2VM_R4.5M  [C_D7]  109.18 64.54 180 bottom
PC1129  22U_0603_6.3V6M  [C_0603]  113.41 71.07 270 top
PC1132  22U_0603_6.3V6M  [C_0603]  100.16 53.36 270 top
PC1133  22U_0603_6.3V6M  [C_0603]  115.83 70.38 270 top
PC1134  22U_0603_6.3V6M  [C_0603]  113.29 74.41 90 top
PC1136  22U_0603_6.3V6M  [C_0603]  123.74 74.06 270 top
PC1137  22U_0603_6.3V6M  [C_0603]  120.43 76.76 180 top
PC1139  22U_0603_6.3V6M  [C_0603]  141.77 69.05 180 top
PC1140  22U_0603_6.3V6M  [C_0603]  141.03 74.03 180 top
PC1141  22U_0603_6.3V6M  [C_0603]  141.44 71.59 180 top
PC1142  22U_0603_6.3V6M  [C_0603]  141.03 72.82 180 top
PC1143  22U_0603_6.3V6M  [C_0603]  99.64 50.96 270 bottom
PC1144  22U_0603_6.3V6M  [C_0603]  97.23 50.96 270 top
PC1145  22U_0603_6.3V6M  [C_0603]  98.43 50.96 270 top
PC1146  22U_0603_6.3V6M  [C_0603]  100.84 50.96 270 bottom
PC1147  1U_0201_6.3V6M  [C_0201]  140.57 75.6 180 top
PC1148  1U_0201_6.3V6M  [C_0201]  140.88 76.86 90 top
PC1149  1U_0201_6.3V6M  [C_0201]  142.54 74.72 0 top
PC1150  1U_0201_6.3V6M  [C_0201]  141.46 76.86 90 top
PC1151  1U_0201_6.3V6M  [C_0201]  141.19 75.55 270 top
PC1152  1U_0201_6.3V6M  [C_0201]  142.26 70.91 0 top
PC1153  1U_0201_6.3V6M  [C_0201]  140.58 74.96 180 top
PC1175  22U_0603_6.3V6M  [C_0603]  111.44 73.44 270 top
PC1176  22U_0603_6.3V6M  [C_0603]  110.24 73.44 270 top
PC1177  22U_0603_6.3V6M  [C_0603]  109.8 71.08 270 top
PC1178  22U_0603_6.3V6M  [C_0603]  101.37 53.36 270 bottom
PC1179  22U_0603_6.3V6M  [C_0603]  111 71.07 270 top
PC1180  22U_0603_6.3V6M  [C_0603]  101.37 53.36 270 top
PC1181  22U_0603_6.3V6M  [C_0603]  124.4 69.26 270 top
PC1201  0.1U_0402_25V6  [C_0402]  47.5 87.98 180 top
PC1202  1000P_0402_50V7K  [C_0402]  53.84 86.46 90 top
PC1203  100P_0402_50V8J  [C_0402]  52.06 86.46 90 top
PC1204  1500P_0402_50V7K  [C_0402]  53.51 86.42 180 bottom
PC1205  0.47U_0603_25V6K  [C_0603]  52.57 84.72 180 bottom
PC1206  0.022U_0402_25V7K  [C_0402]  47.54 75.65 90 top
PC1207  0.01U_0402_25V7K  [C_0402]  68.32 85.46 180 top
PC1208  0.1U_0402_25V6  [C_0402]  59.51 82.66 180 top
PC1209  10U 10V M X5R 0402  [C_0402]  44.42 88.86 0 top
PC1210  100P_0402_50V8J  [C_0402]  45.33 90.64 180 top
PC1211  2.2U 25V M X5R 0402  [C_0402]  46.96 89.87 0 top
PC1212  0.1U 25V M X5R 0402  [C_0402]  51.6 88.35 90 bottom
PC1213  0.1U_0402_25V6  [C_0402]  28.62 52.59 90 top
PC1214  1000P_0402_50V7K  [C_0402]  35.86 47.84 180 top
PC1215  100P_0402_50V8J  [C_0402]  35.86 46.95 180 top
PC1216  1500P_0402_50V7K  [C_0402]  40.2 46.39 270 top
PC1217  0.47U_0603_25V6K  [C_0603]  40.43 44.28 270 top
PC1218  0.022U_0402_25V7K  [C_0402]  48.18 49.23 90 top
PC1219  0.01U_0402_25V7K  [C_0402]  47.41 31.07 180 top
PC1220  0.1U_0402_25V6  [C_0402]  44.14 34.02 180 top
PC1221  10U 10V M X5R 0402  [C_0402]  34.99 35.17 270 top
PC1222  100P_0402_50V8J  [C_0402]  37.81 34.12 0 top
PC1223  2.2U 25V M X5R 0402  [C_0402]  35.05 38.01 180 top
PC1224  0.1U 25V K X5R 0402  [C_0402]  34.18 36.15 90 top
PC1283  100P_0402_50V8J  [C_0402]  47.49 88.88 180 top
PC1284  100P_0402_50V8J  [C_0402]  35.09 53.48 90 top
PC1285  1500P_0402_50V7K  [C_0402]  63.15 85.43 270 bottom
PC1321  220U_D7_2VM_R4.5M  [C_D7]  96.8 70.44 270 top
PC1322  22U_0603_6.3V6M  [C_0603]  126.79 72.54 270 top
PC1323  22U_0603_6.3V6M  [C_0603]  130.17 68 0 top
PC1324  22U_0603_6.3V6M  [C_0603]  128.61 71.31 0 top
PC1325  22U_0603_6.3V6M  [C_0603]  126.87 68 180 top
PC1326  22U_0603_6.3V6M  [C_0603]  127.82 68 0 top
PC1327  22U_0603_6.3V6M  [C_0603]  128.61 72.53 0 top
PC1328  1U_0201_6.3V6M  [C_0201]  120.92 71.3 90 top
PC1329  1U_0201_6.3V6M  [C_0201]  119.1 72.32 270 top
PC1330  1U_0201_6.3V6M  [C_0201]  128.77 76.83 0 top
PC1331  1U_0201_6.3V6M  [C_0201]  127.57 76.83 0 top
PC1332  1U_0201_6.3V6M  [C_0201]  126.38 76.84 0 top
PC1333  1U_0201_6.3V6M  [C_0201]  130.61 65.83 270 top
PC1334  1U_0201_6.3V6M  [C_0201]  128.77 65.84 270 top
PC1335  1U_0402_10V6K  [C_0402]  87.2 72.39 90 bottom
PC1336  1U_0402_10V6K  [C_0402]  89.55 66.15 90 bottom
PC1337  1U_0402_10V6K  [C_0402]  94.25 59.31 90 bottom
PD1  -  [TVNST52302AB0_SOT523-3]  69.51 44.54 0 top
PD2  -  [TVNST52302AB0_SOT523-3]  69.51 42.06 0 top
PD3  BAS40CW SOT-323  [DB3J315E0L_SMINI3-F2-B3]  285.59 23.3 270 bottom
PD901  SDMK0340L-7-F_SOD323-2~D  [SDMK0340L-7-F_SOD323-2]  66.62 34.3 0 top
PD903  -  [RB520SM-30T2R_EMD2-2]  65.65 30.77 0 top
PD904  -  [RB520SM-30T2R_EMD2-2]  66.62 32.52 0 top
PD905  BAT54CW-7-F SOT-323 DII  [BAT54CW_SOT323-3]  66.71 37.8 90 top
PD906  SMF4L22A SOD123FL-2  [SMF22A-SOD123FL-2-S]  54.49 56.32 90 top
PD1201  -  [SDMK0340L-7-F_SOD323-2]  47.03 86.32 90 bottom
PD1202  B2100AF-13 SMAF-2  [B2100AF-13_SMAF2]  45.31 75.56 90 bottom
PD1205  B2100AF-13 SMAF-2  [B2100AF-13_SMAF2]  48.3 46.19 180 bottom
PD1206  -  [SDMK0340L-7-F_SOD323-2]  32.79 38.69 270 top
PH601  470K_0402_5%_B25/50 4700K  [R_0402]  86.81 76.64 180 bottom
PH602  10K_0402_5%_B25/50 4250K  [R_0402]  98.27 73.55 270 bottom
PH603  470K_0402_5%_B25/50 4700K  [R_0402]  86.02 61.96 0 bottom
PH604  10KB_0402_5%  [R_0402]  99.17 53.14 180 bottom
PH605  10K_0402_5%_B25/50 4250K  [R_0402]  101.09 62.66 180 bottom
PJP1  PAD-OPEN1X1M  [JUMP_43X39]  155.49 92.67 0 top
PJP2  PAD-OPEN1X1M  [JUMP_43X39]  176.95 80.57 180 bottom
PJP3  PAD-OPEN1X3M  [JUMP_43X118]  157.9 91.82 270 bottom
PJP4  PAD-OPEN1X1M  [JUMP_43X39]  175.05 60.66 180 top
PJP5  PAD-OPEN1X1M  [JUMP_43X39]  22.65 79.33 90 top
PJP6  PAD-OPEN1X1M  [JUMP_43X39]  23.16 83.98 270 top
PJP8  PAD-OPEN 1X3M  [JUMP_43X118]  28.74 77.56 180 top
PJP10  PAD-OPEN 1X3M  [JUMP_43X118]  31.41 41.23 90 top
PJP12  PAD-OPEN1X1M  [JUMP_43X39]  228.26 28.28 0 bottom
PJP14  PAD-OPEN1X2M  [JUMP_43X79]  283.23 65.17 180 top
PJP15  PAD-OPEN1X1M  [JUMP_43X39]  256.51 36.9 270 top
PJP16  PAD-OPEN1X1M  [JUMP_43X39]  256.51 30.05 270 top
PJP17  PAD-OPEN1X2M  [JUMP_43X79]  253.27 36.4 90 top
PJP18  PAD-OPEN1X1M  [JUMP_43X39]  253.58 30.05 270 top
PJP19  PAD-OPEN1X1M  [JUMP_43X39]  281.58 42.02 90 top
PJP20  PAD-OPEN1X1M  [JUMP_43X39]  263.05 49.32 90 top
PJP21  PAD-OPEN1X1M  [JUMP_43X39]  260.76 49.32 90 top
PJP22  PAD-OPEN1X1M  [JUMP_43X39]  263.7 69.68 0 top
PJP31  PAD-OPEN1X2M  [JUMP_43X79]  31.29 21.89 90 top
PJP35  PAD-OPEN1X1M  [JUMP_43X39]  173.78 37.18 270 top
PJP36  PAD-OPEN1X2M  [JUMP_43X79]  230.59 34.88 180 top
PJP38  PAD-OPEN1X1M  [JUMP_43X39]  236.44 38.57 0 top
PJP39  PAD-OPEN1X3M  [JUMP_43X118]  20.53 35.77 180 top
PJP40  PAD-OPEN1X2M  [JUMP_43X79]  200.41 41.97 180 top
PJP41  PAD-OPEN1X3M  [JUMP_43X118]  209.81 42.38 0 top
PJP42  PAD-OPEN1X1M  [JUMP_43X39]  225.77 44.51 90 top
PJP100  PAD-OPEN 1X2M~D  [JUMP_43X79]  72.68 50.11 270 bottom
PJP101  PAD-OPEN 1X2M~D  [JUMP_43X79]  50.21 77.05 270 bottom
PJP102  -  [JUMP_43X118]  74.08 35.77 180 top
PJP103  -  [JUMP_43X118]  48.18 63.42 90 top
PJP200  -  [JUMP_43X118]  91.31 35.77 0 bottom
PJP201  -  [JUMP_43X39]  89.37 39.71 0 top
PJP202  PAD-OPEN 1X2M~D  [JUMP_43X79]  81.28 48.09 0 bottom
PJP301  PAD-OPEN 1X2M~D  [JUMP_43X79]  56.59 75.89 0 bottom
PJP302  -  [JUMP_43X118]  60.07 65.13 180 top
PJP391  PAD-OPEN1X1M  [JUMP_43X39]  168.32 49.62 0 top
PJP401  -  [JUMP_43X79]  188.26 28.15 0 top
PJP402  -  [JUMP_43X79]  167.77 27.77 0 bottom
PJP501  PAD-OPEN1X1M  [JUMP_43X39]  206.72 28.91 0 top
PJP502  PAD-OPEN1X1M  [JUMP_43X39]  220.14 28.66 0 top
PJP505  PAD-OPEN1X1M  [JUMP_43X39]  76.28 54.68 0 top
PJP506  PAD-OPEN1X1M  [JUMP_43X39]  77.56 47.58 0 top
PJP601  PAD-OPEN 4X4M  [JUMP_43X118]  67.59 58.81 180 bottom
PJP602  PAD-OPEN 1X2M~D  [JUMP_43X79]  74.6 60.45 135 bottom
PJP603  PAD-OPEN1X1M  [JUMP_43X39]  82.05 53.22 90 bottom
PJP901  PAD-OPEN 4X4M  [JUMP_43X118-NPM]  55.5 58.63 180 bottom
PJP1201  PAD-OPEN 1X2M~D  [JUMP_43X79]  50.72 82.84 0 top
PJP1202  PAD-OPEN 1X2M~D  [JUMP_43X79]  40.65 49.37 0 top
PL1  FBMJ4516HS720NT_2P  [TAIYO_FBMJ4516HS720NT_2P]  58.44 48.24 0 top
PL2  FBMJ4516HS720NT_2P  [TAIYO_FBMJ4516HS720NT_2P]  58.44 50.51 0 top
PL100  2.2UH_PCMB062D-2R2MS_7A_20%  [CYNTE_PCMB062D-2R2MS_2P]  73.97 39.81 270 bottom
PL101  1UH +-20% PCMB062D-1R0MS 9A  [CYNTE_PCMB062D-2R2MS_2P]  53.49 65.19 180 bottom
PL201  1UH_PCMB062D-1R0MS_9A_20%  [CYNTE_PCMB062D-1R0MS_2P]  83.86 38.8 270 bottom
PL301  1UH_PCMB051H-1R0MS_8A_20%  [CYNTE_PCMB051H-1R0MS_2P]  60.37 68.17 270 bottom
PL402  1UH_1277AS-H-1R0N-P2_3.3A_30%  [MAG_MLV-FY12N1R0M-O1L_2P]  180.64 27.58 0 top
PL404  1UH_1277AS-H-1R0N-P2_3.3A_30%  [MAG_MLV-FY12N1R0M-O1L_2P]  163.09 28.62 0 bottom
PL405  3A_Z120_40M_0603_2P  [3A_Z120_0603_2P]  169.92 29.54 0 top
PL406  3A_Z120_40M_0603_2P  [3A_Z120_0603_2P]  164.43 38.01 0 top
PL407  3A_Z120_40M_0603_2P  [3A_Z120_0603_2P]  171.47 32.44 270 top
PL408  3A_Z120_40M_0603_2P  [3A_Z120_0603_2P]  162.26 35.84 0 bottom
PL501  1UH_1277AS-H-1R0N-P2_3.3A_30%  [MAG_MLV-FY12N1R0M-O1L_2P]  213.22 28.31 0 top
PL502  3A_Z120_40M_0603_2P  [3A_Z120_0603_2P]  205.44 26.66 0 top
PL602  9A Z80 10M 1812_2P  [9A_Z80_1812_2P-NPM]  68.94 58.81 180 bottom
PL610  0.15UH_MMD-06BDER15MEM1L_27A_20%  [L_7X7X2P4_M]  102.17 77.74 180 bottom
PL612  0.15UH_MMD-06BDER15MEM1L_27A_20%  [L_7X7X2P4_M]  102.64 58.39 180 bottom
PL613  0.15UH_MMD-06BDER15MEM1L_27A_20%  [L_7X7X2P4_M]  97.94 67.03 180 bottom
PL614  0.47UH MMD-05AHNR47MEX2L 10.5A  [MAG_MMD05CZR47M_4P]  96.01 51.74 180 bottom
PL901  1UH_PCMB051H-1R0MS_8A_20%  [CYNTE_PCMB051H-1R0MS_2P]  57.13 58.63 180 bottom
PL902  1UH_PCMB102T-1R0MS_10.8A_20%  [CYNTE_PCMB102T-1R0MS_2P]  52.87 50.5 0 bottom
PL1201  FBMA-L11-201209_0805  [TAI-T_HCB2012KF-121T50_2P]  48.81 87.83 270 top
PL1202  FBMA-L11-201209_0805  [TAI-T_HCB2012KF-121T50_2P]  36.75 52.66 0 top
PL1203  FBMA-L11-201209_0805  [TAI-T_HCB2012KF-121T50_2P]  50.59 87.83 270 top
PL1204  FBMA-L11-201209_0805  [TAI-T_HCB2012KF-121T50_2P]  36.75 50.86 0 top
PQ614  PE642DT_DFN3X3  [AON7934_DFN3X3A8-10]  87.76 52.32 180 bottom
PQ904  AOE6936_DFN5X6E8-10  [AOE6930_DFN5X6E8-10]  66.08 53.58 0 bottom
PQ905  AOE6936_DFN5X6E8-10  [AOE6930_DFN5X6E8-10]  45.51 56.56 0 bottom
PQ906  EMZB08P03V_DFN8-5  [FDMC6679AZ_MLP8-5]  59.83 54.56 270 top
PQ909  L2N7002WT1G 1N SC-70-3  [DMN65D8LW-7_SOT323-3]  52.1 30.92 270 top
PQ1200  EMZB08P03V_DFN8-5  [FDMC6679AZ_MLP8-5]  54.04 81.06 0 top
PQ1201  -  [DMN65D8LDW-7_SOT363-6]  48.66 87.82 90 bottom
PQ1202  EMZB08P03V_DFN8-5  [FDMC6679AZ_MLP8-5]  51.48 78.1 90 top
PQ1203  EMZB08P03V_DFN8-5  [FDMC6679AZ_MLP8-5]  44.14 76.75 0 top
PQ1204  AO3409 P-CHANNEL SOT-23  [SI2303CDS-T1-GE3_SOT23-3]  40.81 76.82 180 top
PQ1205  L2N7002WT1G 1N SC-70-3  [DMN65D8LW-7_SOT323-3]  61.59 79.73 90 top
PQ1206  L2N7002WT1G 1N SC-70-3  [DMN65D8LW-7_SOT323-3]  65.48 81.08 0 top
PQ1207  -  [DMN65D8LDW-7_SOT363-6]  58.76 83.6 0 top
PQ1208  L2N7002WT1G 1N SC-70-3)  [DMN65D8LW-7_SOT323-3]  40.46 88.59 0 top
PQ1209  L2N7002WT1G 1N SC-70-3  [DMN65D8LW-7_SOT323-3]  57.56 86.97 90 bottom
PQ1210  EMZB08P03V_DFN8-5  [FDMC6679AZ_MLP8-5]  39.18 43.68 90 top
PQ1211  EMZB08P03V_DFN8-5  [FDMC6679AZ_MLP8-5]  43.42 46.41 270 top
PQ1212  EMZB08P03V_DFN8-5  [FDMC6679AZ_MLP8-5]  46.69 48.37 90 top
PQ1213  AO3409 P-CHANNEL SOT-23  [SI2303CDS-T1-GE3_SOT23-3]  43.46 53.06 0 top
PQ1214  L2N7002WT1G 1N SC-70-3  [DMN65D8LW-7_SOT323-3]  36.55 42.03 0 top
PQ1215  L2N7002WT1G 1N SC-70-3  [DMN65D8LW-7_SOT323-3]  40.12 41.74 0 top
PQ1216  -  [DMN65D8LDW-7_SOT363-6]  43.52 35.88 0 top
PQ1217  -  [DMN65D8LDW-7_SOT363-6]  48.18 43.97 0 top
PQ1218  L2N7002WT1G 1N SC-70-3  [DMN65D8LW-7_SOT323-3]  36.17 30.18 270 top
PQ1219  L2N7002WT1G 1N SC-70-3)  [DMN65D8LW-7_SOT323-3]  43.35 36.66 180 bottom
PQ1220  -  [DMN65D8LDW-7_SOT363-6]  67.05 86.77 0 bottom
PQ1221  -  [DMN65D8LDW-7_SOT363-6]  64.25 86.63 0 bottom
PQ1222  -  [DMN65D8LDW-7_SOT363-6]  70.89 86.73 0 bottom
PQ1223  -  [DMN65D8LDW-7_SOT363-6]  73.83 86.52 0 bottom
PQ1224  -  [DMN65D8LDW-7_SOT363-6]  39.77 83.83 270 top
PQ1225  AO3409 P-CHANNEL SOT-23  [NTR4502PT1G_SOT23-3]  49.83 83 270 bottom
PQ1226  -  [DMN65D8LDW-7_SOT363-6]  48.46 32.46 90 top
PQ1227  AO3409 P-CHANNEL SOT-23  [NTR4502PT1G_SOT23-3]  42.8 41.6 270 top
PQ1228  L2N7002WT1G 1N SC-70-3  [DMN65D8LW-7_SOT323-3]  61.16 88.28 180 bottom
PR1  100K_0402_5%  [R_0402]  67 45.61 0 top
PR2  1K_0402_5%  [R_0402]  288.97 22.87 90 bottom
PR100  0_0603_5%  [R0603_0OHM]  73.51 42.76 0 top
PR102  499K_0402_1%  [R_0402]  55.47 73.49 0 bottom
PR103  499K_0402_1%  [R_0402]  55.47 72.6 0 bottom
PR104  0_0402_5%  [R0402_0OHM]  78.36 41.31 270 bottom
PR105  0_0402_5%  [R0402_0OHM]  79.24 41.31 270 bottom
PR106  4.7_1206_5%  [R_1206]  72.43 39.71 0 top
PR107  100K_0402_5%  [R_0402]  62.54 77.94 0 top
PR108  1K_0402_5%  [R_0402]  78.35 43.27 180 bottom
PR111  0_0603_5%  [R0603_0OHM]  49.83 68.79 270 top
PR112  4.7_1206_5%  [R_1206]  52.18 64.98 0 top
PR113  100K_0402_5%  [R_0402]  54.21 75.12 270 bottom
PR114  0_0402_5%  [R0402_0OHM]  78.73 47.46 180 bottom
PR116  1M_0402_1%  [R_0402]  77.48 45.25 0 bottom
PR117  1K_0402_5%  [R_0402]  56.38 70.82 180 bottom
PR119  0_0402_5%  [R0402_0OHM]  63.45 77.05 180 top
PR120  0_0402_5%  [R0402_0OHM]  53.32 74.2 90 bottom
PR202  4.7_1206_5%  [R_1206]  83.29 37.04 0 top
PR203  0_0603_5%  [R0603_0OHM]  81.89 37.3 180 top
PR204  102K_0402_1%  [R_0402]  80.48 43.9 0 bottom
PR205  0_0402_5%  [R_0402]  81.45 45.68 180 bottom
PR206  100K_0402_1%  [R_0402]  80.61 43.01 0 bottom
PR207  0_0402_5%  [R_0402]  79.98 45.55 0 top
PR208  0_0402_5%  [R0402_0OHM]  88.89 47.08 180 top
PR209  1M_0402_5%  [R_0402]  87.98 45.3 0 top
PR210  0_0402_5%  [R0402_0OHM]  90.67 43.65 180 top
PR212  1M_0402_5%  [R_0402]  89.76 42.76 0 top
PR302  1M_0402_1%  [R_0402]  64.51 75.4 180 bottom
PR303  4.7_1206_5%  [R_1206]  56.56 67.12 270 bottom
PR304  0_0402_5%  [R0402_0OHM]  59.55 71.45 180 bottom
PR306  21.5K_0402_1%  [R_0402]  65.41 70.53 90 bottom
PR307  0_0402_5%  [R_0402]  66.51 74.38 0 top
PR308  1K_0402_5%  [R_0402]  66.4 72.31 180 bottom
PR310  0_0402_5%  [R_0402]  67.43 75.27 180 top
PR311  31.6K_0402_1%  [R_0402]  65.49 73.19 0 bottom
PR312  0_0402_5%  [R0402_0OHM]  63.59 76.29 0 bottom
PR402  0_0402_5%  [R0402_0OHM]  168.83 25.99 0 top
PR403  1M_0402_1%  [R_0402]  173.6 26.31 180 top
PR404  0_0402_5%  [R_0402]  170.73 28.08 270 top
PR405  4.7_0603_5%  [R_0603]  180.48 29.68 0 top
PR406  0_0402_5%  [R0402_0OHM]  168.73 34.44 180 bottom
PR407  1M_0402_1%  [R_0402]  167.81 35.34 0 bottom
PR408  0_0402_5%  [R_0402]  167.23 40.85 270 top
PR409  4.7_0603_5%  [R_0603]  161.96 28 180 bottom
PR410  0_0402_5%  [R_0402]  168.7 32.6 180 bottom
PR411  0_0402_5%  [R_0402]  165.52 42.12 180 top
PR412  0_0402_5%  [R_0402]  179.37 31.45 90 top
PR413  10K_0402_1%  [R_0402]  175.4 32.42 0 top
PR414  10K_0402_1%  [R_0402]  174.44 30.64 270 top
PR415  10K_0402_1%  [R_0402]  176.32 31.52 180 top
PR416  10K_0402_1%  [R_0402]  173.55 29.73 90 top
PR417  10K_0402_1%  [R_0402]  165.47 40.09 270 top
PR418  10K_0402_1%  [R_0402]  165.4 41.23 0 top
PR419  10K_0402_1%  [R_0402]  164.51 39.2 90 top
PR420  10K_0402_1%  [R_0402]  166.31 39.07 0 top
PR421  0_0402_5%  [R_0402]  182.03 31.33 180 top
PR422  0_0402_5%  [R_0402]  180.26 31.45 90 top
PR423  0_0402_5%  [R0402_0OHM]  155.66 29.19 270 top
PR424  100K_0402_1%  [R_0402]  156.57 29.19 270 top
PR425  0_0402_5%  [R0402_0OHM]  169.84 28.08 270 top
PR426  0_0402_5%  [R0402_0OHM]  170.55 33.99 180 top
PR427  0_0402_5%  [R_0402]  177.21 31.53 0 top
PR428  1M_0402_1%  [R_0402]  156.57 30.13 180 top
PR501  20K_0402_1%  [R_0402]  209.97 26.25 90 top
PR502  4.7_0603_5%  [R_0603]  213.08 30.45 0 top
PR504  0_0402_5%  [R0402_0OHM]  209.27 32.42 270 top
PR505  1M_0402_1%  [R_0402]  210.39 31.44 0 top
PR506  10K_0402_1%  [R_0402]  208.2 27.14 270 top
PR513  0_0402_5%  [R0402_0OHM]  81.11 55.86 90 top
PR514  1M_0402_1%  [R_0402]  80.24 56.78 180 top
PR515  12.7K_0402_1%  [R_0402]  81.19 49.13 90 top
PR516  10.2K_0402_1%  [R_0402]  80.28 50.06 270 top
PR517  100K_0402_5%  [R_0402]  207.79 31.91 180 top
PR601  45.3_0402_1%  [R_0402]  65.45 78.65 0 bottom
PR602  0_0402_5%  [R0402_0OHM]  67.61 76.67 180 top
PR603  0_0402_5%  [R0402_0OHM]  67.48 73.11 180 top
PR604  75_0402_1%  [R_0402]  65.45 77.77 0 bottom
PR605  100_0402_1%  [R_0402]  65.45 76.89 0 bottom
PR606  0_0402_5%  [R0402_0OHM]  88.37 48.91 0 top
PR608  88.7K_0402_1%  [R_0402]  69.21 75.27 0 top
PR610  10K_0402_1%  [R_0402]  69.48 82.07 270 bottom
PR611  1.87K_0402_1%  [R_0402]  69.2 74.39 0 top
